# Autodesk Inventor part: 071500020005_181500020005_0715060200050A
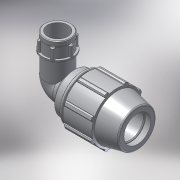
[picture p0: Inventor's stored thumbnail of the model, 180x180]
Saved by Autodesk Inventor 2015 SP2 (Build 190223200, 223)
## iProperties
Created: 2017-02
Part Number: 071500020005_181500020005_0715060200050A
Material: PVC-Piping
Description: PLASSON 90° ELBOW FEMALE ADAPTOR 20-1/2"
Document SubType Name: Modeling
Designer: KIM
Mass: 92.6774 g
Surface Area: 199.44 cm^2
Volume: 66.1981 cm^3
Density: 1.4 g/cm^3
Appearance: Smooth - White
Author: KIM
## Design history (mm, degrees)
derived "07150.ipt"
feature "Solid1::07150.ipt"
tag "TaggingFeature1"
body "Solid1"
other parameters: "d4" = 6.5, "d5" = 19.5, "d7" = 48, "d9" = 11.14286, "d11" = 2.6, "d13" = 120 deg, "d15" = 12 deg, "d16" = 41.76, "d18" = 1, "d19" = 35 deg, "d20" = 17.5 deg, "d21" = 44.64, "d23" = 0, "d25" = 360 deg, "d27" = 0.96, "d33" = 0.4, "d42" = 28.86, "d43" = 1.44, "d46" = 0.6, "d51" = 78, "d68" = 2.6, "d73" = 24.2203, "d74" = 19, "d75" = 27.85335, "d76" = 18.631, "d77" = 20.9, "d79" = 7.4524, "d80" = 0.55893, "d83" = 0, "d84" = 0, "d91" = 36, "d93" = 54, "d94" = 18.631, "d95" = 13.0417, "d96" = 7.8, "d97" = 50 deg, "d98" = 16.7679, "d99" = 0.5, "d100" = 0.5, "d101" = 6.33333, "d102" = 24.2203, "d103" = 16.15, "d104" = 0, "d108" = 360 deg, "d110" = 0.72661, "E_" = 48, "A_" = 78, "l_" = 54, "l_2" = 19, "Rp_" = 18.631, "d105" = 3.63304
